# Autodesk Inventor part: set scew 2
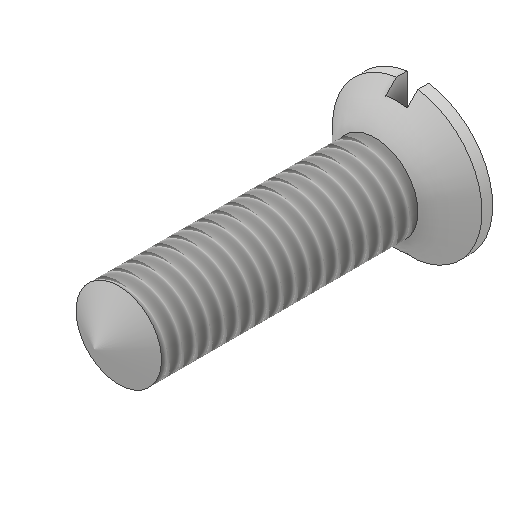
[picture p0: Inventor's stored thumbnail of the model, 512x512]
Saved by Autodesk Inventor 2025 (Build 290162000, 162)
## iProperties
Created: 2016-06
Part Number: set scew 2
Material: Generic
Document SubType Name: Modeling
Designer: CADCIM
Density: 1 g/cm^3
Appearance: Default
Mass: 0.690766 g
Surface Area: 5.88069 cm^2
Volume: 0.690766 cm^3
Author: CADCIM
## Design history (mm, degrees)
sketch "Sketch1"
  geometry: C1 r 3 at (0, 0); 1 further point
  constraints: 1 centre point, 1 coincident
  dimensions: "d0" = 6 diameter of C1
extrude "Extrusion1" new body sketch "Sketch1" distance "d1" = 18; taper "d2" = 0 deg
revolve "Revolution1" stored, may be unused: angle "d7" = 90 deg
sketch "Sketch3"
  geometry: C1 r 5.25 at (0, 0); 1 further point
  constraints: 1 centre point, 1 coincident
  dimensions: "d8" = 10.5 diameter of C1
extrude "Extrusion2" sketch "Sketch3" distance "d9" = 26.75; taper "d10" = 0 deg
sketch "Sketch4"
  geometry: L1 (-0.75, 8.347)-(0.75, 8.347); L2 (0.75, 8.347)-(0.75, -8.125); L3 (0.75, -8.125)-(-0.75, -8.125); L4 (-0.75, -8.125)-(-0.75, 8.347); L5 (0, 0)-(0, 6.165)
  constraints: 10 end point, 3 parallel, 1 horizontal, 1 perpendicular, 1 other
  dimensions: "d11" = 1.5 distance of L1.start L1.end
extrude "Extrusion3" cut sketch "Sketch4" distance "d12" = 1.5; taper "d13" = 0 deg
thread "Thread2" dims "d19" = 10, "d20" = 0
revolve "Revolution3" stored, may be unused: angle "d23" = 90 deg
body "Solid1"
sketch "Sketch5"
  geometry: L1 (0, 0)-(0, 3); L2 (0, 3)-(-1.732, 0); L3 (-1.732, 0)-(0, 0); L4 (0, 3)-(0, -3) reference; 1 further point
  constraints: 6 end point, 2 midpoint, 1 perpendicular, 1 point on line, 1 vertical
  dimensions: "d21" = 60 deg angle of L2 L3; "d22" = 3 distance of L1.start L1.end
sketch "Sketch2"
  geometry: L1 (18, -3)-(18, 3) reference; L2 (18, 0)-(18, -3); L3 (18, -3)-(21, -6); L4 (21, -6)-(21, 0); L5 (21, 0)-(18, 0); 1 further point
  constraints: 8 end point, 2 vertical, 1 midpoint, 1 perpendicular
  dimensions: "d4" = 3 distance of L2.start L2.end; "d5" = 6 distance of L4.end L3.end; "d6" = 3 distance from line of L1.start L4
